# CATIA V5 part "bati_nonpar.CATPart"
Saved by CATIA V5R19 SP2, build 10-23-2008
Part number: bati 
Material "Aucun"
Bounding box of the stored display mesh (mm): x -20 to 20, y -50 to 50, z -4 to 40.312
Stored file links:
  F:\Projet CAO\pièces et assemblages\mécanisme 577\577-SaintAime\577-SaintAime\bati_nonpar.CATPart
  C:\Users\Tilou\Documents\Cours M1\Conception\conception fauroux\Projet CAO\pièces et assemblages\mécanisme 577\mecanisme 577.CATProduct
  C:\Appli\Dassault Systemes\B19\intel_a\startup\materials\French\Catalog.CATMaterial
  C:\Appli\Dassault Systemes\B19\intel_a\startup\materials\solar_panel.jpg
  C:\Appli\Dassault Systemes\B19\intel_a\startup\materials\blue_env_512x512.jpg
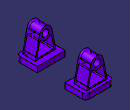
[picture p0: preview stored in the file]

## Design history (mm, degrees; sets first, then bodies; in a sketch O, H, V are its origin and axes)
Set1
  Plane1: type Offset, RefPlane zx-plane, Offset 37, reversed
Body1 (main body)
  Sketch1 on yz-plane, origin (0, 0, 0), H (0, 1, 0), V (0, 0, 1)
    line L1 (-50, 4) -> (-20, 4)
    line L2 (50, 4) -> (50, -4)
    line L3 (50, -4) -> (20, -4)
    line L4 (-50, -4) -> (-50, 4)
    line L5 (-20, 4) -> (-20, -4)
    point P6 (-20, -4)
    point P7 (20, 4)
    line L6 (20, 4) -> (20, -4)
    line L7 (20, 4) -> (50, 4)
    line L8 (-20, -4) -> (-50, -4)
    distance L1 L3 = 8
    distance L6 L2 = 30
    distance L2 L4 = 100
    horizontal: L1 H, L3 H, L7 H, L8 H
    vertical: L2 V, L4 V, L5 V, L6 V
    symmetry: L2 L4 V, L3 L1 H, L6 L5 V
    coincidence: P6 L3, P7 L1, L1 L7, L3 L8
  Pad1: profile Sketch1, direction (1, 0, 0), length 20, mirrored extent
  Sketch2 on Plane1, origin (0, -37, 0), H (-1, 0, 0), V (0, 0, 1)
    line L1 (15, 4) -> (8.8059, 33.3405)
    arc A1 centre (0, 31.4815) radius 9 from (8.8059, 33.3405) to (-8.8059, 33.3405) ccw
    point P3 (0, 31.4815)
    line L2 (-8.8059, 33.3405) -> (-15, 4)
    circle A2 centre (0, 31.4815) radius 5
    line L3 (15, 4) -> (-15, 4)
    reference projected line E1 (40, 4) -> (-40, 4) from edge [face of Pad1 from Sketch1.L4 | face of Pad1 from Sketch1.L1]
    line L4 (-11.3005, 6) -> (11.3005, 6)
    line L5 (12.279, 7.2066) -> (8.5015, 25.0999)
    point P7 (8.0175, 27.3926)
    line L6 (-12.279, 7.2066) -> (-8.5015, 25.0999)
    point P8 (-8.0175, 27.3926)
    arc A3 centre (0, 31.4815) radius 9 from (-6.7708, 25.5522) to (6.7708, 25.5522) ccw
    point P9 (0, 31.4815)
    arc A4 centre (7.5231, 24.8934) radius 1 from (6.7708, 25.5522) to (8.5015, 25.0999) cw
    arc A5 centre (-7.5231, 24.8934) radius 1 from (-6.7708, 25.5522) to (-8.5015, 25.0999) ccw
    arc A6 centre (11.3005, 7) radius 1 from (11.3005, 6) to (12.279, 7.2066) ccw
    arc A7 centre (-11.3005, 7) radius 1 from (-11.3005, 6) to (-12.279, 7.2066) cw
    radius A2 = 5
    length L3 = 30
    radius A1 = 9
    distance L4 L3 = 2
    distance L5 L1 = 2
    radius A4 = 1
    radius A5 = 1
    radius A6 = 1
    radius A7 = 1
    distance A3 A2 = 4
    distance P9 L3 = 27.4815
    tangency: A1 L1, L2 A1, A4 A3, A4 L5, A5 L6, A5 A3, A6 L4, A6 L5, A7 L4, A7 L6
    symmetry: L2 L1 V, L6 L5 V
    coincidence: P3 V, L3 E1, A3 P7, L5 P7, A3 P8, L6 P8
    concentricity: A2 A1, A3 A1
    horizontal: L3 H, L4 H
    parallelism: L6 L2
  Pad2: profile Sketch2, direction (0, 1, 0), length 9, mirrored extent
  Mirror1: of Pad2, Sketch2, about zx-plane
  Fillet1: radius 5, on edge [face of Pad1 from Sketch1.L4 | end face of Pad1]; edge [face of Pad1 from Sketch1.L2 | end face of Pad1]; edge [start face of Pad1 | face of Pad1 from Sketch1.L2]; edge [start face of Pad1 | face of Pad1 from Sketch1.L4]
